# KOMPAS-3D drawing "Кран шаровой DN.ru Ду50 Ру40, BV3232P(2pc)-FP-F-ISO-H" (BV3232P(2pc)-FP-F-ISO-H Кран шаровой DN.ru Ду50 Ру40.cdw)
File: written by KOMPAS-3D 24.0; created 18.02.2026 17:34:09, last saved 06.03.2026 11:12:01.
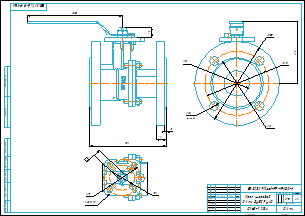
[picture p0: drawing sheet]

Document properties: Автор: R2D2; Форматы листов документа: A2; Полное имя файла: BV3232P(2pc)-FP-F-ISO-H Кран шаровой DN.ru Ду50 Ру40.m3d; Масса: 8.78; Наименование: Кран шаровой DN.ru Ду50 Ру40; Количество листов документа: 1; Примечание: D160-22134

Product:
- Part/product: Кран шаровой DN.ru Ду50 Ру40  | designation BV3232P(2pc)-FP-F-ISO-H
    Масса: 8.78
    Раздел спецификации: Прочие изделия
    Форматы листов документа: A2
    Примечание: D160-22134

Views: Проекционный вид 2, Проекционный вид 3
Referenced files in E:\Работа\Зайцев\BV3232P(2pc)-FP-F-ISO-H Кран шаровой DN.ru Ду15-300 Ру16-40\DN50 PN40\исходные материалы\: BV3232P(2pc)-FP-F-ISO-H Кран шаровой DN.ru Ду50 Ру40.m3d
Referenced files in E:\Работа\Зайцев\Для компаса\: чертеж DN.ru А3.cdt
Referenced files in E:\Работа\Зайцев\BV3232P(2pc)-FP-F-ISO-H Кран шаровой DN.ru Ду15-300 Ру16-40\DN50 PN40\: BV3232P(2pc)-FP-F-ISO-H Кран шаровой DN.ru Ду50 Ру40.m3d
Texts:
  BV3232P(2pc)-FP-F-ISO-H
  ISO 5211
  чертеж DN.ru А3.cdt
  Кран шаровой
  DN.ru Ду50 Ру40
  Кран шаровой DN.ru Ду50 Ру40
  BV3232P(2pc)-FP-F-ISO-H Кран шаровой DN.ru Ду50 Ру40
Dimensions and other numbers on the sheet: 0; 3; 4; 120; 165; 125; 102; 50; 18; 4 отв.; 70; 14; 1:1; 1; 2; 8,78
